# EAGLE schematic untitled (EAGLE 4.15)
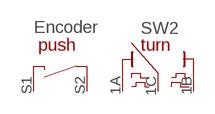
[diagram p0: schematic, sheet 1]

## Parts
SW2  ENC-SW  [ENC-SW]
Unconnected: SW2.1A SW2.1B SW2.1C SW2.S1 SW2.S2

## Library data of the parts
SW2 = piher:ENC-SW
